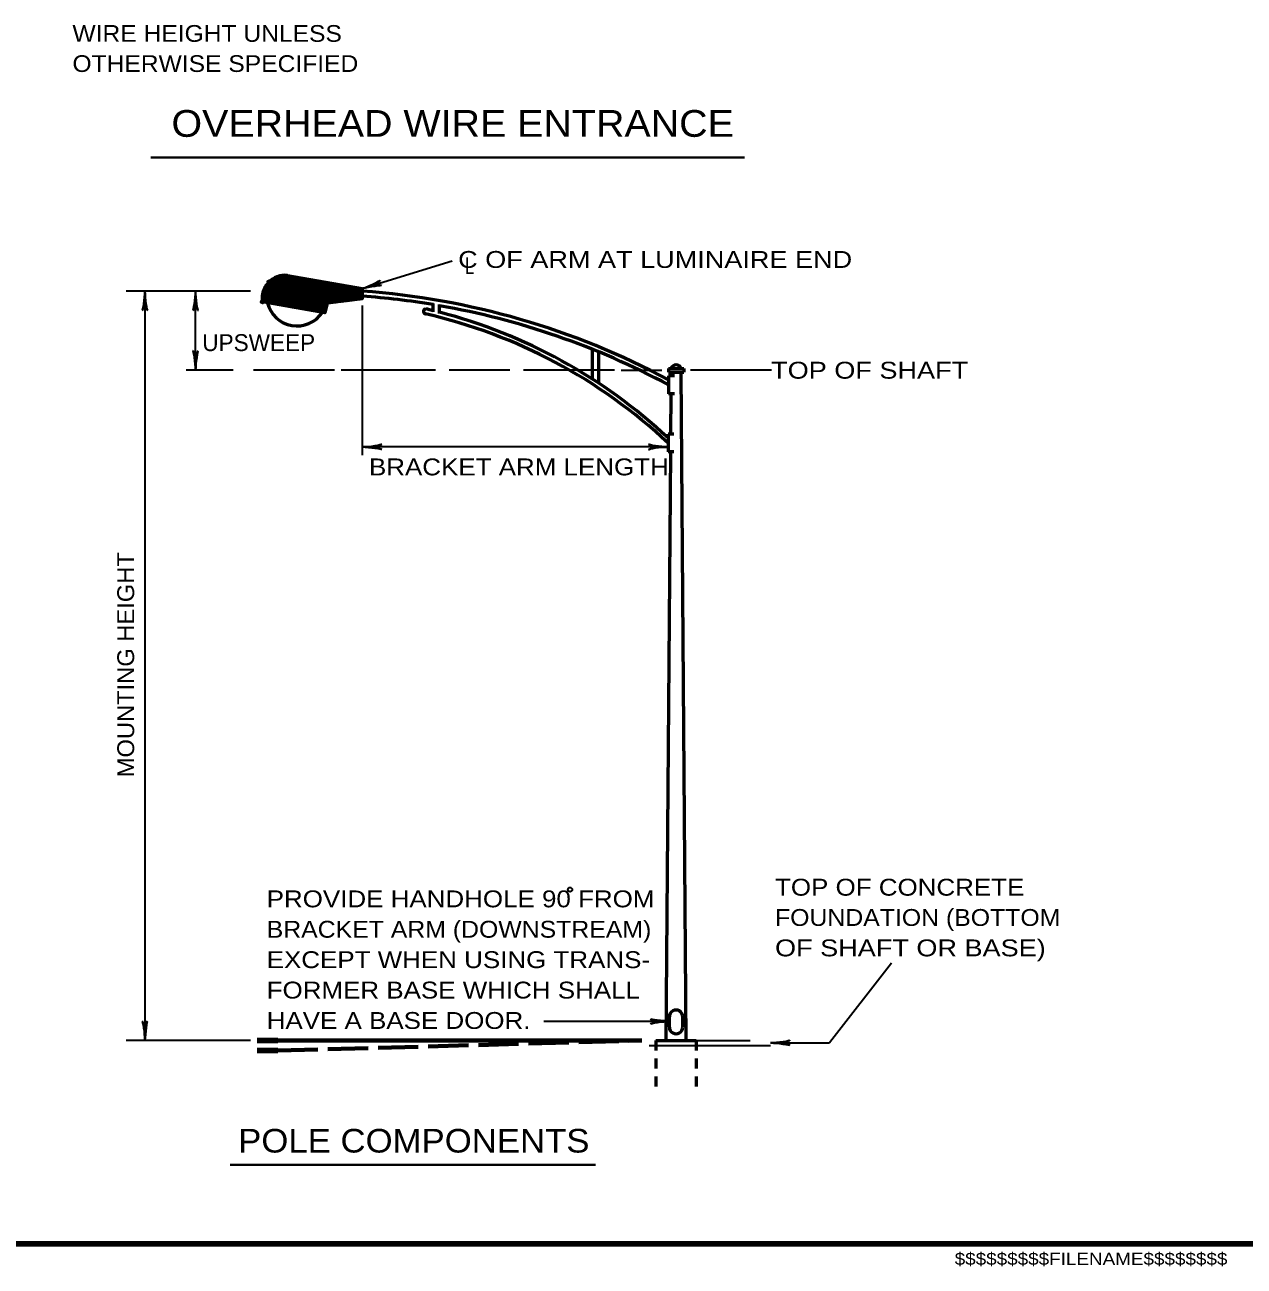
# Model space of a CAD drawing. Extents: x 6460 to 7173, y 270 to 723.
# Drawn here: x 6801.5 to 6983.6, y 276 to 461.4 of the extents above; entities that cross this region are included whole.
import ezdxf

# ---------------------------------------------------------------- set-up
doc = ezdxf.new("R2010")
doc.units = 0
doc.header["$PDMODE"] = 32
doc.header["$PDSIZE"] = 0.5
doc.linetypes.add('LONG_DASHED', pattern=[7.5, 6, -1.5])
doc.linetypes.add('SHORT_DASHED', pattern=[2.7, 1.5, -1.2])
doc.layers.add('1', color=7, linetype='Continuous', lineweight=35)

msp = doc.modelspace()

# ---------------------------------------------------------------- linework, layer by layer
at = {"layer": '1', "lineweight": 40}
for p, q in [((6820.262, 441.584), (6908.953, 441.584)), ((6832.11, 291.178), (6886.69, 291.178))]:
    msp.add_line(p, q, dxfattribs=at)
at = {"layer": '1'}
for p, q in [((6851.87, 421.998), (6865.29, 426.138)), ((6835.19, 421.618), (6816.59, 421.618)), ((6819.39, 421.618), (6819.39, 309.738)), ((6826.95, 409.818), (6826.95, 421.618)), ((6851.87, 419.478), (6851.87, 397.158)), ((6832.59, 409.818), (6825.55, 409.818)), ((6847.71, 409.818), (6835.63, 409.818)), ((6862.83, 409.818), (6848.73, 409.818)), ((6873.93, 409.818), (6864.85, 409.818)), ((6889.55, 409.818), (6875.95, 409.818)), ((6890.55, 409.818), (6896.61, 409.818)), ((6912.99, 409.818), (6900.89, 409.818)), ((6897.55, 398.358), (6851.87, 398.358)), ((6930.91, 321.278), (6921.65, 309.378)), ((6897.81, 312.578), (6878.97, 312.578)), ((6835.19, 309.738), (6816.59, 309.738)), ((6901.77, 309.738), (6909.83, 309.738)), ((6894.71, 308.978), (6912.85, 308.978)), ((6912.85, 309.378), (6921.65, 309.378))]:
    msp.add_line(p, q, dxfattribs=at)
at = {"layer": '1', "lineweight": 53}
for p, q in [((6836.99, 421.318), (6839.59, 423.898)), ((6837.03, 421.438), (6839.45, 423.858)), ((6837.09, 421.598), (6839.29, 423.818)), ((6837.13, 421.758), (6839.13, 423.758)), ((6837.21, 421.958), (6838.95, 423.678)), ((6837.31, 422.158), (6838.73, 423.578)), ((6837.47, 422.418), (6838.47, 423.418)), ((6837.51, 421.718), (6839.73, 423.918)), ((6837.63, 421.718), (6839.85, 423.958)), ((6837.73, 421.718), (6839.97, 423.958)), ((6837.83, 421.718), (6840.09, 423.978)), ((6837.95, 421.718), (6840.21, 423.978)), ((6838.05, 421.718), (6840.31, 423.978)), ((6838.15, 421.718), (6840.43, 423.978)), ((6838.27, 421.718), (6840.53, 423.978)), ((6838.37, 421.718), (6840.63, 423.978)), ((6838.47, 421.718), (6840.73, 423.978)), ((6838.59, 421.718), (6840.81, 423.958)), ((6838.69, 421.718), (6840.91, 423.938)), ((6838.79, 421.718), (6840.99, 423.918)), ((6838.91, 421.718), (6841.09, 423.898)), ((6839.01, 421.718), (6841.19, 423.898)), ((6839.11, 421.718), (6841.27, 423.878)), ((6839.23, 421.718), (6841.37, 423.858)), ((6839.33, 421.718), (6841.45, 423.838)), ((6839.43, 421.718), (6841.55, 423.818)), ((6839.55, 421.718), (6841.63, 423.818)), ((6839.65, 421.718), (6841.73, 423.798)), ((6839.77, 421.718), (6841.81, 423.778)), ((6839.87, 421.718), (6841.91, 423.758)), ((6839.97, 421.718), (6841.99, 423.738)), ((6840.09, 421.718), (6842.09, 423.738)), ((6840.19, 421.718), (6842.19, 423.718)), ((6840.29, 421.718), (6842.27, 423.698)), ((6840.41, 421.718), (6842.37, 423.678)), ((6840.51, 421.718), (6842.45, 423.658)), ((6840.61, 421.718), (6842.55, 423.658)), ((6840.73, 421.718), (6842.63, 423.638)), ((6840.83, 421.718), (6842.73, 423.618)), ((6840.93, 421.718), (6842.81, 423.598)), ((6841.05, 421.718), (6842.91, 423.578)), ((6841.15, 421.718), (6842.99, 423.558)), ((6841.25, 421.718), (6843.09, 423.558)), ((6841.37, 421.718), (6843.19, 423.538)), ((6841.47, 421.718), (6843.27, 423.518)), ((6841.57, 421.718), (6843.37, 423.498)), ((6841.69, 421.718), (6843.45, 423.478)), ((6841.79, 421.718), (6843.55, 423.478)), ((6841.89, 421.718), (6843.63, 423.458)), ((6842.01, 421.718), (6843.73, 423.438)), ((6842.11, 421.718), (6843.81, 423.418)), ((6842.21, 421.718), (6843.91, 423.398)), ((6842.33, 421.718), (6843.99, 423.398)), ((6842.43, 421.718), (6844.09, 423.378)), ((6842.55, 421.718), (6844.19, 423.358)), ((6842.65, 421.718), (6844.27, 423.338)), ((6842.75, 421.718), (6844.37, 423.318)), ((6842.87, 421.718), (6844.45, 423.318)), ((6842.97, 421.718), (6844.55, 423.298)), ((6843.07, 421.718), (6844.63, 423.278)), ((6843.19, 421.718), (6844.73, 423.258)), ((6843.29, 421.718), (6844.81, 423.238)), ((6843.39, 421.718), (6844.91, 423.238)), ((6843.51, 421.718), (6844.99, 423.218)), ((6843.61, 421.718), (6845.09, 423.198)), ((6843.71, 421.718), (6845.19, 423.178)), ((6843.83, 421.718), (6845.27, 423.158)), ((6843.93, 421.718), (6845.37, 423.158)), ((6844.03, 421.718), (6845.45, 423.138)), ((6844.15, 421.718), (6845.55, 423.118)), ((6844.25, 421.718), (6845.63, 423.098)), ((6844.35, 421.718), (6845.73, 423.078)), ((6844.47, 421.718), (6845.81, 423.078)), ((6844.57, 421.718), (6845.91, 423.058)), ((6844.67, 421.718), (6845.99, 423.038)), ((6844.79, 421.718), (6846.09, 423.018)), ((6844.89, 421.718), (6846.19, 422.998)), ((6844.99, 421.718), (6846.27, 422.998)), ((6845.11, 421.718), (6846.37, 422.978)), ((6845.21, 421.718), (6846.45, 422.958)), ((6845.31, 421.718), (6846.55, 422.938)), ((6845.43, 421.718), (6846.63, 422.918)), ((6845.53, 421.718), (6846.73, 422.918)), ((6845.65, 421.718), (6846.81, 422.898)), ((6845.75, 421.718), (6846.91, 422.878)), ((6845.85, 421.718), (6846.99, 422.858)), ((6845.97, 421.718), (6847.09, 422.838)), ((6846.07, 421.718), (6847.17, 422.838)), ((6846.17, 421.718), (6847.27, 422.818)), ((6846.29, 421.718), (6847.37, 422.798)), ((6846.39, 421.718), (6847.45, 422.778)), ((6846.49, 421.718), (6847.55, 422.758)), ((6846.61, 421.718), (6847.63, 422.758)), ((6846.71, 421.718), (6847.73, 422.738)), ((6846.81, 421.718), (6847.81, 422.718)), ((6846.93, 421.718), (6847.91, 422.698)), ((6847.03, 421.718), (6847.99, 422.678)), ((6847.13, 421.718), (6848.09, 422.678)), ((6847.25, 421.718), (6848.17, 422.658)), ((6847.35, 421.718), (6848.27, 422.638)), ((6836.91, 420.798), (6837.65, 421.538)), ((6836.91, 420.678), (6837.75, 421.538)), ((6836.91, 420.578), (6837.87, 421.538)), ((6836.91, 420.478), (6837.97, 421.538)), ((6836.91, 420.358), (6838.07, 421.538)), ((6836.91, 420.278), (6838.19, 421.538)), ((6836.93, 420.918), (6837.53, 421.538)), ((6836.93, 420.178), (6838.29, 421.538)), ((6836.93, 420.078), (6838.39, 421.538)), ((6836.95, 421.038), (6837.49, 421.598)), ((6836.97, 421.178), (6837.49, 421.698)), ((6836.99, 420.018), (6838.51, 421.538)), ((6837.09, 419.998), (6838.61, 421.538)), ((6837.17, 419.998), (6838.71, 421.538)), ((6837.27, 419.978), (6838.83, 421.538)), ((6837.35, 419.958), (6838.93, 421.538)), ((6837.45, 419.938), (6839.03, 421.538)), ((6837.53, 419.918), (6839.15, 421.538)), ((6837.63, 419.918), (6839.25, 421.538)), ((6837.73, 419.898), (6839.35, 421.538)), ((6837.81, 419.878), (6839.47, 421.538)), ((6837.91, 419.858), (6839.57, 421.538)), ((6837.99, 419.838), (6839.67, 421.538)), ((6838.09, 419.838), (6839.79, 421.538)), ((6838.17, 419.818), (6839.89, 421.538)), ((6838.27, 419.798), (6839.99, 421.538)), ((6838.35, 419.778), (6840.11, 421.538)), ((6838.45, 419.758), (6840.21, 421.538)), ((6838.53, 419.758), (6840.31, 421.538)), ((6838.63, 419.738), (6840.43, 421.538)), ((6838.71, 419.718), (6840.53, 421.538)), ((6838.81, 419.698), (6840.65, 421.538)), ((6838.91, 419.678), (6840.75, 421.538)), ((6838.99, 419.678), (6840.85, 421.538)), ((6839.09, 419.658), (6840.97, 421.538)), ((6839.17, 419.638), (6841.07, 421.538)), ((6839.27, 419.618), (6841.17, 421.538)), ((6839.35, 419.598), (6841.29, 421.538)), ((6839.45, 419.598), (6841.39, 421.538)), ((6839.53, 419.578), (6841.49, 421.538)), ((6839.63, 419.558), (6841.61, 421.538)), ((6839.71, 419.538), (6841.71, 421.538)), ((6839.81, 419.518), (6841.81, 421.538)), ((6839.91, 419.518), (6841.93, 421.538)), ((6839.99, 419.498), (6842.03, 421.538)), ((6840.09, 419.478), (6842.13, 421.538)), ((6840.17, 419.458), (6842.25, 421.538)), ((6840.27, 419.438), (6842.35, 421.538)), ((6840.35, 419.438), (6842.45, 421.538)), ((6840.45, 419.418), (6842.57, 421.538)), ((6840.53, 419.398), (6842.67, 421.538)), ((6840.63, 419.378), (6842.77, 421.538)), ((6840.71, 419.358), (6842.89, 421.538)), ((6840.81, 419.338), (6842.99, 421.538)), ((6840.91, 419.338), (6843.09, 421.538)), ((6840.99, 419.318), (6843.21, 421.538)), ((6841.09, 419.298), (6843.31, 421.538)), ((6841.17, 419.278), (6843.43, 421.538)), ((6841.27, 419.258), (6843.53, 421.538)), ((6841.35, 419.258), (6843.63, 421.538)), ((6841.45, 419.238), (6843.75, 421.538)), ((6841.53, 419.218), (6843.85, 421.538)), ((6841.63, 419.198), (6843.95, 421.538)), ((6841.71, 419.178), (6844.07, 421.538)), ((6841.81, 419.178), (6844.17, 421.538)), ((6841.91, 419.158), (6844.27, 421.538)), ((6841.99, 419.138), (6844.39, 421.538)), ((6842.09, 419.118), (6844.49, 421.538)), ((6842.17, 419.098), (6844.59, 421.538)), ((6842.27, 419.098), (6844.71, 421.538)), ((6842.35, 419.078), (6844.81, 421.538)), ((6842.45, 419.058), (6844.91, 421.538)), ((6842.53, 419.038), (6845.03, 421.538)), ((6842.63, 419.018), (6845.13, 421.538)), ((6842.71, 419.018), (6845.23, 421.538)), ((6842.81, 418.998), (6845.35, 421.538)), ((6842.91, 418.978), (6845.45, 421.538)), ((6842.99, 418.958), (6845.55, 421.538)), ((6843.09, 418.938), (6845.67, 421.538)), ((6843.17, 418.938), (6845.77, 421.538)), ((6843.27, 418.918), (6845.87, 421.538)), ((6843.35, 418.898), (6845.99, 421.538)), ((6843.45, 418.878), (6846.09, 421.538)), ((6843.53, 418.858), (6846.21, 421.538)), ((6843.63, 418.858), (6846.31, 421.538)), ((6843.71, 418.838), (6846.41, 421.538)), ((6843.81, 418.818), (6846.53, 421.538)), ((6843.91, 418.798), (6846.63, 421.538)), ((6843.99, 418.778), (6846.73, 421.538)), ((6844.09, 418.778), (6846.85, 421.538)), ((6844.17, 418.758), (6846.95, 421.538)), ((6844.27, 418.738), (6847.05, 421.538)), ((6844.35, 418.718), (6847.17, 421.538)), ((6844.45, 418.698), (6847.27, 421.538)), ((6844.53, 418.698), (6847.37, 421.538)), ((6844.63, 418.678), (6847.49, 421.538)), ((6844.71, 418.658), (6847.59, 421.538)), ((6844.81, 418.638), (6847.69, 421.538)), ((6844.91, 418.618), (6847.81, 421.538)), ((6844.99, 418.618), (6847.91, 421.538)), ((6845.09, 418.598), (6848.01, 421.538)), ((6845.17, 418.578), (6848.13, 421.538)), ((6845.27, 418.558), (6848.23, 421.538)), ((6846.65, 419.858), (6848.33, 421.538)), ((6846.79, 419.858), (6848.45, 421.538)), ((6846.91, 419.878), (6848.55, 421.538)), ((6847.03, 419.898), (6848.65, 421.538)), ((6847.15, 419.918), (6848.77, 421.538)), ((6847.27, 419.918), (6848.87, 421.538)), ((6847.39, 419.938), (6848.97, 421.538)), ((6847.45, 421.718), (6848.37, 422.618)), ((6847.51, 419.958), (6849.09, 421.538)), ((6847.57, 421.718), (6848.45, 422.598)), ((6847.63, 419.978), (6849.19, 421.538)), ((6847.67, 421.718), (6848.55, 422.598)), ((6847.75, 419.978), (6849.31, 421.538)), ((6847.77, 421.718), (6848.63, 422.578)), ((6847.87, 419.998), (6849.41, 421.538)), ((6847.89, 421.718), (6848.73, 422.558)), ((6847.99, 421.718), (6848.81, 422.538)), ((6847.99, 420.018), (6849.51, 421.538)), ((6848.09, 421.718), (6848.91, 422.518)), ((6848.13, 420.038), (6849.63, 421.538)), ((6848.21, 421.718), (6848.99, 422.518)), ((6848.25, 420.038), (6849.73, 421.538)), ((6848.31, 421.718), (6849.09, 422.498)), ((6848.37, 420.058), (6849.83, 421.538)), ((6848.43, 421.718), (6849.17, 422.478)), ((6848.49, 420.078), (6849.95, 421.538)), ((6848.53, 421.718), (6849.27, 422.458)), ((6848.61, 420.098), (6850.05, 421.538)), ((6848.63, 421.718), (6849.37, 422.438)), ((6848.73, 420.098), (6850.15, 421.538)), ((6848.75, 421.718), (6849.45, 422.438)), ((6848.85, 421.718), (6849.55, 422.418)), ((6848.85, 420.118), (6850.27, 421.538)), ((6848.95, 421.718), (6849.63, 422.398)), ((6848.97, 420.138), (6850.37, 421.538)), ((6849.07, 421.718), (6849.73, 422.378)), ((6849.09, 420.158), (6850.47, 421.538)), ((6849.17, 421.718), (6849.81, 422.358)), ((6849.21, 420.158), (6850.59, 421.538)), ((6849.27, 421.718), (6849.91, 422.358)), ((6849.33, 420.178), (6850.69, 421.538)), ((6849.39, 421.718), (6849.99, 422.338)), ((6849.47, 420.198), (6850.79, 421.538)), ((6849.49, 421.718), (6850.09, 422.318)), ((6849.59, 421.718), (6850.17, 422.298)), ((6849.59, 420.218), (6850.91, 421.538)), ((6849.71, 421.718), (6850.27, 422.278)), ((6849.71, 420.218), (6851.01, 421.538)), ((6849.81, 421.718), (6850.37, 422.278)), ((6849.83, 420.238), (6851.11, 421.538)), ((6849.91, 421.718), (6850.45, 422.258)), ((6849.95, 420.258), (6851.23, 421.538)), ((6850.03, 421.718), (6850.55, 422.238)), ((6850.07, 420.278), (6851.33, 421.538)), ((6850.13, 421.718), (6850.63, 422.218)), ((6850.19, 420.278), (6851.43, 421.538)), ((6850.23, 421.718), (6850.73, 422.198)), ((6850.31, 420.298), (6851.87, 421.858)), ((6850.35, 421.718), (6850.81, 422.198)), ((6850.43, 420.318), (6851.87, 421.758)), ((6850.45, 421.718), (6850.91, 422.178)), ((6850.55, 421.718), (6850.99, 422.158)), ((6850.55, 420.338), (6851.87, 421.638)), ((6850.67, 421.718), (6851.09, 422.138)), ((6850.69, 420.338), (6851.87, 421.538)), ((6850.77, 421.718), (6851.17, 422.118)), ((6850.81, 420.358), (6851.87, 421.438)), ((6850.87, 421.718), (6851.27, 422.118)), ((6850.93, 420.378), (6851.87, 421.318)), ((6850.99, 421.718), (6851.37, 422.098)), ((6851.05, 420.398), (6851.87, 421.218)), ((6851.09, 421.718), (6851.45, 422.078)), ((6851.17, 420.398), (6851.87, 421.118)), ((6851.21, 421.718), (6851.55, 422.058)), ((6851.29, 420.418), (6851.87, 420.998)), ((6851.31, 421.718), (6851.63, 422.038)), ((6851.41, 421.718), (6851.73, 422.038)), ((6851.41, 420.438), (6851.87, 420.898)), ((6851.49, 421.698), (6851.81, 422.018)), ((6851.49, 421.598), (6851.87, 421.958)), ((6851.53, 420.458), (6851.87, 420.798)), ((6845.35, 418.538), (6846.61, 419.798)), ((6845.45, 418.538), (6846.59, 419.658)), ((6845.53, 418.518), (6846.55, 419.518)), ((6845.63, 418.498), (6846.51, 419.398)), ((6845.71, 418.478), (6846.49, 419.258)), ((6845.81, 418.458), (6846.45, 419.118)), ((6845.89, 418.458), (6846.43, 418.978)), ((6851.65, 420.458), (6851.87, 420.678)), ((6851.77, 420.478), (6851.87, 420.578)), ((6862.45, 418.518), (6862.45, 419.798)), ((6863.41, 418.278), (6863.41, 419.638)), ((6845.99, 418.438), (6846.39, 418.838)), ((6846.09, 418.418), (6846.35, 418.698)), ((6846.17, 418.398), (6846.33, 418.558)), ((6846.27, 418.378), (6846.29, 418.418)), ((6886.27, 408.478), (6886.27, 412.938)), ((6887.21, 407.878), (6887.21, 412.538)), ((6897.61, 410.098), (6899.89, 410.098)), ((6897.61, 410.098), (6897.61, 409.538)), ((6899.89, 410.098), (6899.89, 409.538)), ((6897.61, 409.538), (6899.89, 409.538)), ((6898.49, 408.958), (6897.61, 408.958)), ((6897.61, 408.958), (6897.61, 406.318)), ((6897.99, 409.538), (6897.99, 408.958)), ((6900.25, 309.738), (6899.51, 409.538)), ((6898.49, 406.318), (6897.61, 406.318)), ((6897.97, 406.318), (6897.93, 400.258)), ((6898.43, 400.258), (6897.55, 400.258)), ((6897.55, 400.258), (6897.55, 397.618)), ((6897.91, 397.618), (6897.23, 309.738)), ((6898.43, 397.618), (6897.55, 397.618)), ((6897.75, 311.758), (6897.75, 313.258)), ((6899.75, 311.758), (6899.75, 313.258)), ((6895.73, 309.738), (6901.77, 309.738))]:
    msp.add_line(p, q, dxfattribs=at)
at = {"layer": '1', "lineweight": 106}
for p, q in [((6836.19, 309.738), (6839.23, 309.738)), ((6836.19, 308.218), (6839.23, 308.218))]:
    msp.add_line(p, q, dxfattribs=at)
at = {"layer": '1', "lineweight": 70}
msp.add_line((6839.23, 309.738), (6893.65, 309.738), dxfattribs=at)
at = {"layer": '1', "linetype": 'LONG_DASHED', "lineweight": 70}
msp.add_line((6839.23, 308.218), (6893.65, 309.738), dxfattribs=at)
at = {"layer": '1', "linetype": 'SHORT_DASHED', "lineweight": 53}
for p, q in [((6895.73, 309.738), (6895.73, 301.678)), ((6901.77, 309.738), (6901.77, 301.678))]:
    msp.add_line(p, q, dxfattribs=at)
at = {"layer": '1', "lineweight": 158}
msp.add_line((7167.871, 279.382), (6508.204, 279.382), dxfattribs=at)
at = {"layer": '1', "lineweight": 53}
msp.add_lwpolyline([(6840.71, 423.978), (6851.87, 421.998), (6851.87, 420.498), (6846.63, 419.838), (6846.29, 418.378), (6836.95, 420.038)], dxfattribs=at)
msp.add_lwpolyline([(6837.49, 421.718), (6851.49, 421.718), (6851.49, 421.538), (6837.49, 421.538)], close=True, dxfattribs=at)
at = {"layer": '1'}
msp.add_circle((6882.902, 332.255), 0.325, dxfattribs=at)
at = {"layer": '1', "lineweight": 53}
for centre, radius, start, end in [((6840.361, 420.534), 3.456, 84.23953, 188.38162), ((6843.679, 307.63), 114.289, 61.84402, 85.88743), ((6843.679, 306.874), 114.289, 80.54208, 85.88743), ((6842.122, 421.001), 4.57, 193.94762, 326.05059), ((6861.388, 418.601), 0.383, 99.37484, 260.62516), ((6843.798, 342.391), 78.568, 76.2603, 77.11012), ((6843.679, 306.874), 114.289, 61.84402, 80.06146), ((6861.5, 418.85), 0.651, 235.53017, 254.38288), ((6843.798, 341.635), 78.568, 46.83897, 77.11012), ((6843.798, 342.391), 78.568, 46.83897, 75.54976), ((6898.747, 409.817), 0.802, 20.3922, 159.6078), ((6898.747, 313.286), 0.993, 358.58875, 181.41125), ((6898.747, 311.713), 0.993, 178.58875, 1.41125)]:
    msp.add_arc(centre, radius, start, end, dxfattribs=at)
at = {"layer": '1', "lineweight": 40}
for centre, major_axis, ratio, start_param, end_param in [((6852.844, 422.593), (-1.674, -0.68), 0.122415, 0.8963533, 3.1415927), ((6819.185, 420.496), (0.177, 1.77), 0.07063, 3.1407148, 5.41811), ((6819.677, 420.525), (-0.157, 1.8), 0.122415, 0.8963533, 3.1415927), ((6826.746, 420.496), (0.177, 1.77), 0.07063, 3.1407148, 5.41811), ((6827.237, 420.525), (-0.157, 1.8), 0.122415, 0.8963533, 3.1415927), ((6853.017, 422.132), (1.744, 0.352), 0.07063, 6.2823074, 8.5597026), ((6826.68, 410.913), (0.157, -1.8), 0.122415, 0.8963533, 3.1415927), ((6827.172, 410.942), (-0.177, -1.77), 0.07063, 3.1407148, 5.41811), ((6852.975, 398.641), (-1.8, -0.157), 0.122415, 0.8963533, 3.1415927), ((6852.975, 398.641), (-1.8, -0.157), 0.122415, 0.8963533, 3.1415927), ((6896.414, 398.576), (1.77, -0.177), 0.07063, 3.1407148, 5.41811), ((6896.414, 398.576), (1.77, -0.177), 0.07063, 3.1407148, 5.41811), ((6853.005, 398.149), (-1.77, 0.177), 0.07063, 3.1407148, 5.41811), ((6853.005, 398.149), (-1.77, 0.177), 0.07063, 3.1407148, 5.41811), ((6896.443, 398.084), (1.8, 0.157), 0.122415, 0.8963533, 3.1415927), ((6896.443, 398.084), (1.8, 0.157), 0.122415, 0.8963533, 3.1415927), ((6819.12, 310.837), (0.157, -1.8), 0.122415, 0.8963533, 3.1415927), ((6819.612, 310.867), (-0.177, -1.77), 0.07063, 3.1407148, 5.41811), ((6896.717, 312.303), (1.8, 0.157), 0.122415, 0.8963533, 3.1415927), ((6896.688, 312.795), (1.77, -0.177), 0.07063, 3.1407148, 5.41811), ((6913.955, 309.653), (-1.8, -0.157), 0.122415, 0.8963533, 3.1415927), ((6913.985, 309.161), (-1.77, 0.177), 0.07063, 3.1407148, 5.41811)]:
    msp.add_ellipse(centre, major_axis=major_axis, ratio=ratio, start_param=start_param, end_param=end_param, dxfattribs=at)
at = {"layer": '1'}
for p in [(6837.95, 422.998), (6836.95, 420.038)]:
    msp.add_point(p, dxfattribs=at)

# ---------------------------------------------------------------- texts
for s, height, width, p in [('WIRE HEIGHT UNLESS', 2.5, 1.1, (6808.57, 458.859)), ('OTHERWISE SPECIFIED', 2.5, 1.1, (6808.57, 454.359)), ('OVERHEAD WIRE ENTRANCE', 4, 1.1, (6823.365, 444.672)), ('C OF ARM AT LUMINAIRE END', 2.52, 1.2, (6866.19, 425.098)), ('L', 2.52, 0.75, (6867.21, 424.178)), ('TOP OF SHAFT', 2.52, 1.2, (6912.95, 408.558)), ('BRACKET ARM LENGTH', 2.52, 1.15, (6852.87, 394.118)), ('TOP OF CONCRETE', 2.52, 1.15, (6913.53, 331.358)), ('PROVIDE HANDHOLE 90 FROM', 2.52, 1.15, (6837.59, 329.618)), ('FOUNDATION (BOTTOM', 2.52, 1.1, (6913.53, 326.838)), ('BRACKET ARM (DOWNSTREAM)', 2.52, 1.1, (6837.59, 325.078)), ('OF SHAFT OR BASE)', 2.52, 1.2, (6913.53, 322.298)), ('EXCEPT WHEN USING TRANS-', 2.52, 1.15, (6837.59, 320.538)), ('FORMER BASE WHICH SHALL', 2.52, 1.15, (6837.59, 315.998)), ('HAVE A BASE DOOR.', 2.52, 1.15, (6837.59, 311.458)), ('POLE COMPONENTS', 3.528, 1.1, (6833.33, 292.998)), ('$$$$$$$$$FILENAME$$$$$$$$', 1.833, 1.15, (6940.371, 276.215))]:
    msp.add_text(s, height=height, dxfattribs=dict(at, width=width)).set_placement(p)
msp.add_text('UPSWEEP', height=2.52, dxfattribs=at).set_placement((6827.97, 412.678))
at = {"layer": '1', "width": 1.05}
msp.add_text('MOUNTING HEIGHT', height=2.52, rotation=90, dxfattribs=at).set_placement((6817.79, 349.038))

doc.saveas('drawing.dxf')
